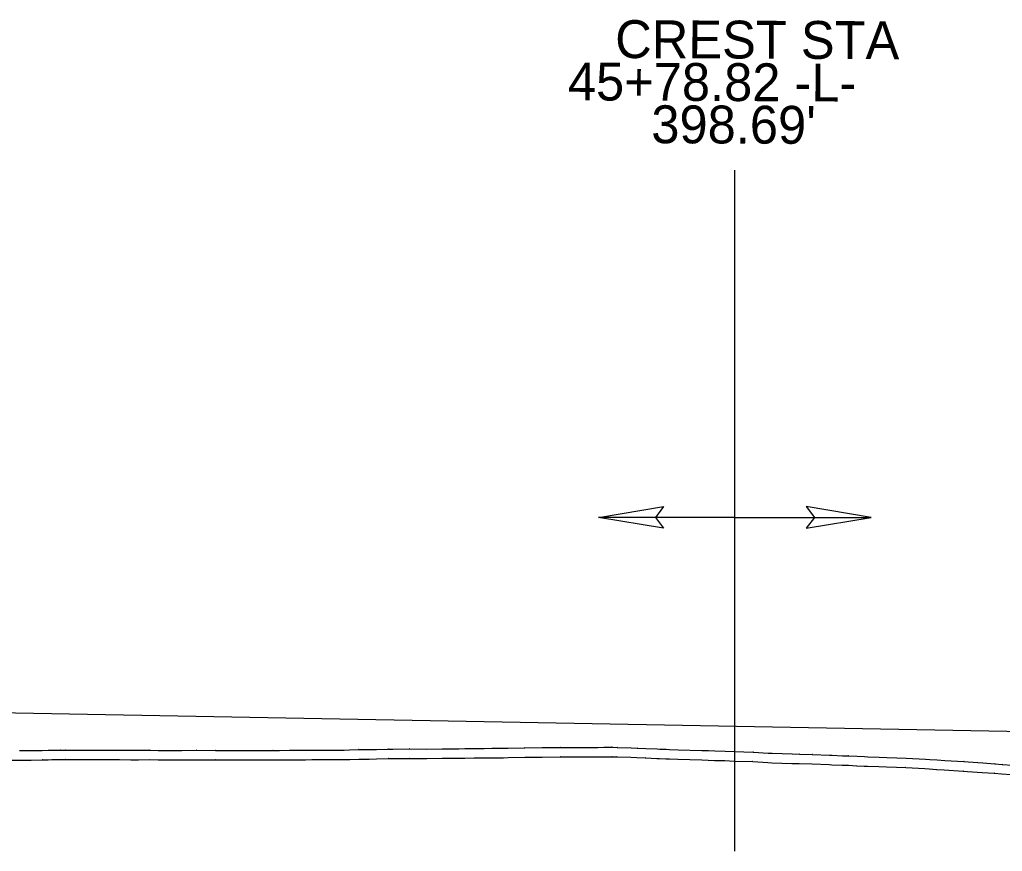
# Model space of a CAD drawing. Extents: x 1625686 to 1640492, y 1161393 to 1175642.
# Drawn here: x 1639525.5 to 1639655.3, y 1175135.6 to 1175245.4 of the extents above; entities that cross this region are included whole.
import ezdxf

# ---------------------------------------------------------------- set-up
doc = ezdxf.new("R2010")
doc.units = 0
for name, color, linetype in [('Prop Plan Preparation Crest', 7, 'Continuous'), ('Prop Vertical Profile Grade', 7, 'Continuous'), ('Scratch_Level_1', 7, 'Continuous')]:
    doc.layers.add(name, color=color, linetype=linetype)

msp = doc.modelspace()

# ---------------------------------------------------------------- linework, layer by layer
at = {"layer": 'Prop Plan Preparation Crest'}
for p, q in [((1639619.93, 1175135.6), (1639619.93, 1175225.54)), ((1639619.93, 1175179.68), (1639601.93, 1175179.68)), ((1639619.93, 1175179.68), (1639637.93, 1175179.68))]:
    msp.add_line(p, q, dxfattribs=at)
for points in [[(1639610.5, 1175178.26), (1639601.93, 1175179.68), (1639610.5, 1175181.11), (1639609.43, 1175179.68)], [(1639629.37, 1175178.26), (1639637.93, 1175179.68), (1639629.37, 1175181.11), (1639630.43, 1175179.68)]]:
    msp.add_lwpolyline(points, close=True, dxfattribs=at)
at = {"layer": 'Prop Vertical Profile Grade'}
msp.add_line((1639521.78, 1175153.93), (1639936.78, 1175146.35), dxfattribs=at)
at = {"layer": 'Scratch_Level_1'}
for p, q in [((1639529.73, 1175148.95), (1639530.89, 1175148.97)), ((1639530.9, 1175148.97), (1639531.48, 1175148.97)), ((1639534.06, 1175148.96), (1639534.55, 1175148.96)), ((1639538.35, 1175148.95), (1639538.66, 1175148.95)), ((1639546.91, 1175148.93), (1639548.84, 1175148.94)), ((1639548.86, 1175148.94), (1639551.36, 1175148.93)), ((1639555.49, 1175148.92), (1639556.43, 1175148.92)), ((1639558.96, 1175148.93), (1639559.78, 1175148.93)), ((1639566.09, 1175148.96), (1639566.57, 1175148.96)), ((1639572.59, 1175149.06), (1639574.12, 1175149.1)), ((1639581.28, 1175149.14), (1639581.75, 1175149.15)), ((1639584.27, 1175149.16), (1639585.47, 1175149.18)), ((1639585.48, 1175149.18), (1639586.81, 1175149.19)), ((1639586.82, 1175149.19), (1639587.83, 1175149.2)), ((1639592.18, 1175149.26), (1639594.47, 1175149.3)), ((1639594.49, 1175149.3), (1639596.87, 1175149.32)), ((1639596.89, 1175149.32), (1639597.93, 1175149.32)), ((1639597.93, 1175149.32), (1639598.37, 1175149.32)), ((1639602.64, 1175149.33), (1639603.68, 1175149.34)), ((1639603.76, 1175149.34), (1639604.39, 1175149.32)), ((1639607.06, 1175149.23), (1639608.16, 1175149.18)), ((1639610.86, 1175149.07), (1639611.32, 1175149.05)), ((1639523.97, 1175147.64), (1639525.48, 1175147.65)), ((1639529.75, 1175147.7), (1639530.91, 1175147.72)), ((1639530.92, 1175147.72), (1639531.5, 1175147.72)), ((1639534.06, 1175147.71), (1639534.55, 1175147.71)), ((1639538.35, 1175147.7), (1639538.66, 1175147.7)), ((1639546.91, 1175147.68), (1639548.84, 1175147.69)), ((1639548.85, 1175147.69), (1639551.36, 1175147.68)), ((1639555.49, 1175147.67), (1639556.43, 1175147.67)), ((1639558.96, 1175147.68), (1639559.78, 1175147.68)), ((1639566.09, 1175147.71), (1639566.57, 1175147.71)), ((1639572.62, 1175147.81), (1639574.15, 1175147.85)), ((1639581.3, 1175147.89), (1639581.76, 1175147.9)), ((1639584.29, 1175147.91), (1639585.49, 1175147.93)), ((1639585.49, 1175147.93), (1639586.83, 1175147.94)), ((1639586.83, 1175147.94), (1639587.84, 1175147.95)), ((1639592.2, 1175148.01), (1639594.49, 1175148.05)), ((1639594.5, 1175148.05), (1639596.88, 1175148.07)), ((1639596.89, 1175148.07), (1639597.93, 1175148.07)), ((1639597.93, 1175148.07), (1639598.37, 1175148.07)), ((1639602.65, 1175148.08), (1639603.69, 1175148.09)), ((1639603.73, 1175148.09), (1639604.36, 1175148.07)), ((1639607, 1175147.98), (1639608.1, 1175147.93)), ((1639610.81, 1175147.82), (1639611.27, 1175147.8)), ((1639628.45, 1175148.43), (1639630.16, 1175148.38)), ((1639630.19, 1175148.38), (1639632.44, 1175148.29)), ((1639634.97, 1175148.2), (1639636.07, 1175148.15)), ((1639642.57, 1175147.9), (1639645.1, 1175147.76)), ((1639628.42, 1175147.18), (1639630.13, 1175147.13)), ((1639630.14, 1175147.13), (1639632.39, 1175147.05)), ((1639634.92, 1175146.95), (1639636.01, 1175146.9)), ((1639642.51, 1175146.65), (1639645.03, 1175146.51)), ((1639654.29, 1175147.15), (1639655.23, 1175147.08)), ((1639654.2, 1175145.91), (1639655.14, 1175145.84))]:
    msp.add_line(p, q, dxfattribs=at)
for points in [[(1639525.48, 1175148.9), (1639525.93, 1175148.9), (1639526.99, 1175148.9), (1639528.45, 1175148.93)], [(1639528.46, 1175148.93), (1639529.24, 1175148.94), (1639529.73, 1175148.95)], [(1639531.52, 1175148.97), (1639533.72, 1175148.96), (1639534.06, 1175148.96)], [(1639534.56, 1175148.96), (1639536.12, 1175148.96), (1639538.35, 1175148.95)], [(1639538.67, 1175148.95), (1639540.18, 1175148.94), (1639541.18, 1175148.94), (1639542.66, 1175148.95)], [(1639542.7, 1175148.95), (1639543.76, 1175148.93), (1639545.76, 1175148.93), (1639546.26, 1175148.93), (1639546.9, 1175148.93)], [(1639551.39, 1175148.93), (1639553.12, 1175148.91), (1639553.88, 1175148.91), (1639555.48, 1175148.92)], [(1639556.44, 1175148.92), (1639557.42, 1175148.92), (1639558.94, 1175148.93)], [(1639559.78, 1175148.93), (1639561.13, 1175148.94), (1639561.75, 1175148.94), (1639563.25, 1175148.94)], [(1639563.25, 1175148.94), (1639564.06, 1175148.95), (1639566.08, 1175148.96)], [(1639566.58, 1175148.96), (1639567.24, 1175148.96), (1639568.32, 1175148.97)], [(1639568.33, 1175148.97), (1639569.05, 1175148.98), (1639570.22, 1175149.02)], [(1639570.26, 1175149.02), (1639571.59, 1175149.03), (1639572.57, 1175149.06)], [(1639574.18, 1175149.1), (1639574.77, 1175149.1), (1639576.93, 1175149.12)], [(1639576.97, 1175149.12), (1639579.23, 1175149.1), (1639581.26, 1175149.14)], [(1639581.78, 1175149.15), (1639583.47, 1175149.15), (1639584.27, 1175149.16)], [(1639587.84, 1175149.2), (1639589.35, 1175149.21), (1639589.99, 1175149.22), (1639592.17, 1175149.26)], [(1639598.37, 1175149.32), (1639599.35, 1175149.32), (1639601.24, 1175149.32)], [(1639601.25, 1175149.32), (1639601.82, 1175149.32), (1639602.64, 1175149.33)], [(1639604.42, 1175149.32), (1639606.23, 1175149.26), (1639607.03, 1175149.23)], [(1639608.17, 1175149.18), (1639609.68, 1175149.11), (1639610.01, 1175149.09), (1639610.85, 1175149.07)], [(1639611.32, 1175149.05), (1639612.46, 1175149.01), (1639615.59, 1175148.92), (1639616.44, 1175148.9)], [(1639616.47, 1175148.9), (1639617.29, 1175148.86), (1639618.65, 1175148.81)], [(1639618.66, 1175148.81), (1639619.89, 1175148.77), (1639622.33, 1175148.69)], [(1639622.39, 1175148.68), (1639624.34, 1175148.57), (1639624.88, 1175148.55), (1639627.48, 1175148.45), (1639628.45, 1175148.43)], [(1639525.48, 1175147.65), (1639525.94, 1175147.65), (1639527, 1175147.65), (1639528.47, 1175147.68)], [(1639528.47, 1175147.68), (1639529.26, 1175147.69), (1639529.75, 1175147.7)], [(1639531.52, 1175147.72), (1639533.71, 1175147.71), (1639534.06, 1175147.71)], [(1639534.56, 1175147.71), (1639536.12, 1175147.71), (1639538.35, 1175147.7)], [(1639538.66, 1175147.7), (1639540.17, 1175147.69), (1639541.19, 1175147.69), (1639542.66, 1175147.7)], [(1639542.69, 1175147.7), (1639543.75, 1175147.68), (1639545.76, 1175147.68), (1639546.27, 1175147.68), (1639546.91, 1175147.68)], [(1639551.37, 1175147.68), (1639553.12, 1175147.66), (1639553.89, 1175147.66), (1639555.49, 1175147.67)], [(1639556.43, 1175147.67), (1639557.43, 1175147.67), (1639558.95, 1175147.68)], [(1639559.78, 1175147.68), (1639561.14, 1175147.69), (1639561.75, 1175147.69), (1639563.25, 1175147.69)], [(1639563.25, 1175147.69), (1639564.06, 1175147.7), (1639566.09, 1175147.71)], [(1639566.58, 1175147.71), (1639567.24, 1175147.71), (1639568.34, 1175147.72)], [(1639568.34, 1175147.72), (1639569.08, 1175147.73), (1639570.26, 1175147.77)], [(1639570.28, 1175147.77), (1639571.62, 1175147.78), (1639572.61, 1175147.81)], [(1639574.18, 1175147.85), (1639574.77, 1175147.85), (1639576.94, 1175147.87)], [(1639576.96, 1175147.87), (1639579.24, 1175147.85), (1639581.28, 1175147.89)], [(1639581.78, 1175147.9), (1639583.48, 1175147.9), (1639584.29, 1175147.91)], [(1639587.85, 1175147.95), (1639589.36, 1175147.96), (1639590.01, 1175147.97), (1639592.2, 1175148.01)], [(1639598.37, 1175148.07), (1639599.36, 1175148.07), (1639601.24, 1175148.07)], [(1639601.25, 1175148.07), (1639601.82, 1175148.07), (1639602.65, 1175148.08)], [(1639604.38, 1175148.07), (1639606.18, 1175148.01), (1639606.99, 1175147.98)], [(1639608.11, 1175147.93), (1639609.62, 1175147.86), (1639609.96, 1175147.84), (1639610.81, 1175147.82)], [(1639611.28, 1175147.8), (1639612.42, 1175147.76), (1639615.55, 1175147.67), (1639616.4, 1175147.65)], [(1639616.42, 1175147.65), (1639617.24, 1175147.61), (1639618.61, 1175147.57)], [(1639618.61, 1175147.57), (1639619.85, 1175147.52), (1639622.29, 1175147.44)], [(1639622.32, 1175147.44), (1639624.28, 1175147.32), (1639624.82, 1175147.3), (1639627.44, 1175147.2), (1639628.41, 1175147.18)], [(1639632.45, 1175148.29), (1639632.77, 1175148.28), (1639634.13, 1175148.22), (1639634.94, 1175148.2)], [(1639636.08, 1175148.15), (1639637.07, 1175148.11), (1639637.5, 1175148.09), (1639638.98, 1175148.03), (1639639.99, 1175148)], [(1639640.01, 1175148), (1639641.34, 1175147.94), (1639642.54, 1175147.9)], [(1639645.11, 1175147.76), (1639645.68, 1175147.72), (1639646.66, 1175147.66)], [(1639646.67, 1175147.66), (1639647.64, 1175147.6), (1639650.16, 1175147.45)], [(1639650.21, 1175147.44), (1639650.74, 1175147.4), (1639652.7, 1175147.26), (1639654.26, 1175147.16)], [(1639632.4, 1175147.04), (1639632.72, 1175147.03), (1639634.09, 1175146.97), (1639634.9, 1175146.95)], [(1639636.02, 1175146.9), (1639637.01, 1175146.86), (1639637.45, 1175146.84), (1639638.93, 1175146.78), (1639639.95, 1175146.75)], [(1639639.96, 1175146.75), (1639641.29, 1175146.7), (1639642.49, 1175146.65)], [(1639645.04, 1175146.51), (1639645.61, 1175146.47), (1639646.58, 1175146.41)], [(1639646.59, 1175146.41), (1639647.56, 1175146.35), (1639650.08, 1175146.2)], [(1639650.11, 1175146.2), (1639650.64, 1175146.15), (1639652.61, 1175146.01), (1639654.18, 1175145.91)], [(1639655.26, 1175147.08), (1639656.54, 1175146.97), (1639657.77, 1175146.87)], [(1639655.15, 1175145.84), (1639656.44, 1175145.73), (1639657.67, 1175145.63)]]:
    msp.add_lwpolyline(points, dxfattribs=at)
for centre, radius, start, end in [((1639528.49, 1175146.43), 2.5, 90.6641, 90.9343), ((1639529.77, 1175146.45), 2.5, 90.9322, 90.9616), ((1639530.93, 1175146.47), 2.5, 90.6257, 90.9322), ((1639531.51, 1175146.47), 2.5, 89.795, 90.6257), ((1639534.06, 1175146.46), 2.5, 89.9627, 89.9921), ((1639534.55, 1175146.46), 2.5, 89.7097, 89.9627), ((1639538.35, 1175146.45), 2.5, 89.8009, 89.8277), ((1639538.65, 1175146.45), 2.5, 89.5758, 89.8009), ((1639542.67, 1175146.45), 2.5, 89.1935, 90.2393), ((1639546.92, 1175146.43), 2.5, 90.2909, 90.3706), ((1639548.85, 1175146.44), 2.5, 89.8045, 90.2909), ((1639551.35, 1175146.43), 2.5, 89.2125, 89.8045), ((1639555.5, 1175146.42), 2.5, 90.0439, 90.4094), ((1639556.43, 1175146.42), 2.5, 89.7047, 90.0439), ((1639558.96, 1175146.43), 2.5, 90.0668, 90.6253), ((1639559.78, 1175146.43), 2.5, 90.0411, 90.0668), ((1639563.26, 1175146.44), 2.5, 90.2138, 90.2664), ((1639566.09, 1175146.46), 2.5, 90.1596, 90.2978), ((1639566.57, 1175146.46), 2.5, 89.8253, 90.1596), ((1639568.36, 1175146.47), 2.5, 90.7413, 90.7638), ((1639570.3, 1175146.52), 2.5, 90.724, 91.759), ((1639572.64, 1175146.56), 2.5, 91.3398, 91.6112), ((1639574.18, 1175146.6), 2.5, 89.9842, 91.3398), ((1639576.95, 1175146.62), 2.5, 89.6324, 90.4608), ((1639581.31, 1175146.64), 2.5, 90.5588, 91.1079), ((1639581.78, 1175146.65), 2.5, 89.9925, 90.5588), ((1639584.31, 1175146.66), 2.5, 90.9028, 90.906), ((1639585.51, 1175146.68), 2.5, 90.6967, 90.9028), ((1639586.84, 1175146.69), 2.5, 90.4696, 90.6967), ((1639587.85, 1175146.7), 2.5, 90.2072, 90.4696), ((1639592.22, 1175146.76), 2.5, 91.0369, 91.1066), ((1639594.51, 1175146.8), 2.5, 90.3844, 91.0369), ((1639596.89, 1175146.82), 2.5, 90.0418, 90.3844), ((1639597.93, 1175146.82), 2.5, 90.0335, 90.0418), ((1639598.37, 1175146.82), 2.5, 90.0136, 90.0335), ((1639601.25, 1175146.82), 2.5, 89.9649, 90.1363), ((1639602.66, 1175146.83), 2.5, 90.4007, 90.4214), ((1639603.7, 1175146.84), 2.5, 88.6188, 90.4007), ((1639604.33, 1175146.82), 2.5, 88.067, 88.6188), ((1639606.95, 1175146.74), 2.5, 87.4145, 88.1466), ((1639608.05, 1175146.69), 2.5, 87.0713, 87.4145), ((1639610.77, 1175146.57), 2.5, 88.0509, 88.1262), ((1639611.23, 1175146.55), 2.5, 87.9622, 88.0509), ((1639616.36, 1175146.4), 2.5, 87.6033, 88.384), ((1639618.57, 1175146.32), 2.5, 87.9354, 88.0572), ((1639622.24, 1175146.19), 2.5, 86.6935, 88.0488), ((1639525.48, 1175146.4), 1.25, 90.1614, 90.1898), ((1639528.49, 1175146.43), 1.25, 90.6641, 90.9343), ((1639529.77, 1175146.45), 1.25, 90.9322, 90.9616), ((1639530.93, 1175146.47), 1.25, 90.6257, 90.9322), ((1639531.51, 1175146.47), 1.25, 89.795, 90.6257), ((1639534.06, 1175146.46), 1.25, 89.9627, 89.9921), ((1639534.55, 1175146.46), 1.25, 89.7097, 89.9627), ((1639538.35, 1175146.45), 1.25, 89.8009, 89.8277), ((1639538.65, 1175146.45), 1.25, 89.5758, 89.8009), ((1639542.67, 1175146.45), 1.25, 89.1935, 90.2393), ((1639546.92, 1175146.43), 1.25, 90.2909, 90.3706), ((1639548.85, 1175146.44), 1.25, 89.8045, 90.2909), ((1639551.35, 1175146.43), 1.25, 89.2125, 89.8045), ((1639555.5, 1175146.42), 1.25, 90.0439, 90.4094), ((1639556.43, 1175146.42), 1.25, 89.7047, 90.0439), ((1639558.96, 1175146.43), 1.25, 90.0668, 90.6253), ((1639559.78, 1175146.43), 1.25, 90.0411, 90.0668), ((1639563.26, 1175146.44), 1.25, 90.2138, 90.2664), ((1639566.09, 1175146.46), 1.25, 90.1596, 90.2978), ((1639566.57, 1175146.46), 1.25, 89.8253, 90.1596), ((1639568.36, 1175146.47), 1.25, 90.7413, 90.7638), ((1639570.3, 1175146.52), 1.25, 90.724, 91.759), ((1639572.64, 1175146.56), 1.25, 91.3398, 91.6112), ((1639574.18, 1175146.6), 1.25, 89.9842, 91.3398), ((1639576.95, 1175146.62), 1.25, 89.6324, 90.4608), ((1639581.31, 1175146.64), 1.25, 90.5588, 91.1079), ((1639581.78, 1175146.65), 1.25, 89.9925, 90.5588), ((1639584.31, 1175146.66), 1.25, 90.9028, 90.906), ((1639585.51, 1175146.68), 1.25, 90.6967, 90.9028), ((1639586.84, 1175146.69), 1.25, 90.4696, 90.6967), ((1639587.85, 1175146.7), 1.25, 90.2072, 90.4696), ((1639592.22, 1175146.76), 1.25, 91.0369, 91.1066), ((1639594.51, 1175146.8), 1.25, 90.3844, 91.0369), ((1639596.89, 1175146.82), 1.25, 90.0418, 90.3844), ((1639597.93, 1175146.82), 1.25, 90.0335, 90.0418), ((1639598.37, 1175146.82), 1.25, 90.0136, 90.0335), ((1639601.25, 1175146.82), 1.25, 89.9649, 90.1363), ((1639602.66, 1175146.83), 1.25, 90.4007, 90.4214), ((1639603.7, 1175146.84), 1.25, 88.6188, 90.4007), ((1639604.33, 1175146.82), 1.25, 88.067, 88.6188), ((1639606.95, 1175146.74), 1.25, 87.4145, 88.1466), ((1639608.05, 1175146.69), 1.25, 87.0713, 87.4145), ((1639610.77, 1175146.57), 1.25, 88.0509, 88.1262), ((1639611.23, 1175146.55), 1.25, 87.9622, 88.0509), ((1639616.36, 1175146.4), 1.25, 87.6033, 88.384), ((1639618.57, 1175146.32), 1.25, 87.9354, 88.0572), ((1639622.24, 1175146.19), 1.25, 86.6935, 88.0488), ((1639628.38, 1175145.93), 2.5, 88.4192, 88.5319), ((1639630.09, 1175145.88), 2.5, 87.7899, 88.4192), ((1639632.34, 1175145.8), 2.5, 87.5644, 87.7899), ((1639634.87, 1175145.7), 2.5, 87.5677, 88.4756), ((1639635.96, 1175145.66), 2.5, 87.3745, 87.5677), ((1639639.92, 1175145.5), 2.5, 87.7552, 88.2076), ((1639642.44, 1175145.4), 2.5, 86.8741, 87.7623), ((1639644.96, 1175145.26), 2.5, 86.4843, 86.8741), ((1639646.5, 1175145.17), 2.5, 86.2052, 86.4914), ((1639650.01, 1175144.95), 2.5, 85.2384, 86.5564), ((1639628.38, 1175145.93), 1.25, 88.4192, 88.5319), ((1639630.09, 1175145.88), 1.25, 87.7899, 88.4192), ((1639632.34, 1175145.8), 1.25, 87.5644, 87.7899), ((1639634.87, 1175145.7), 1.25, 87.5677, 88.4756), ((1639635.96, 1175145.66), 1.25, 87.3745, 87.5677), ((1639639.92, 1175145.5), 1.25, 87.7552, 88.2076), ((1639642.44, 1175145.4), 1.25, 86.8741, 87.7623), ((1639644.96, 1175145.26), 1.25, 86.4843, 86.8741), ((1639646.5, 1175145.17), 1.25, 86.2052, 86.4914), ((1639650.01, 1175144.95), 1.25, 85.2384, 86.5564), ((1639654.11, 1175144.66), 2.5, 85.7693, 86.3738), ((1639655.05, 1175144.59), 2.5, 85.2024, 85.7693), ((1639654.11, 1175144.66), 1.25, 85.7693, 86.3738), ((1639655.05, 1175144.59), 1.25, 85.2024, 85.7693)]:
    msp.add_arc(centre, radius, start, end, dxfattribs=at)

# ---------------------------------------------------------------- texts
at = {"layer": 'Prop Plan Preparation Crest'}
for s, p in [('CREST STA', (1639604.12, 1175240.33)), ('45+78.82 -L-', (1639597.87, 1175234.74)), ("398.69'", (1639608.89, 1175229.09))]:
    msp.add_text(s, height=5, rotation=359.7547, dxfattribs=at).set_placement(p)

doc.saveas('drawing.dxf')
